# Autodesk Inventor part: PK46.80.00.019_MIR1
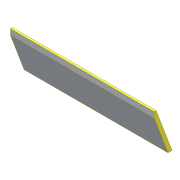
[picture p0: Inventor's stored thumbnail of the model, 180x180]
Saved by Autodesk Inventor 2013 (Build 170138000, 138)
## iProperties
Created: 2005-01
Part Number: PK46.80.00.019_MIR1
Material: Steel, Mild
Document SubType Name: Modeling
Designer: hoeyj
Manufacturer: Standard
Standards Organization: Custom
Density: 7.86 g/cm^3
Mass: 12177.1 g
Surface Area: 1953.57 cm^2
Volume: 1549.25 cm^3
Author: SAlex
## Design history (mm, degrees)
derived "PK46.80.00.019.ipt"
body "Solid1"
tag "TaggingFeature2"
feature "DerivedBody::PK46.80.00.019.ipt" dims "d0" = 10
